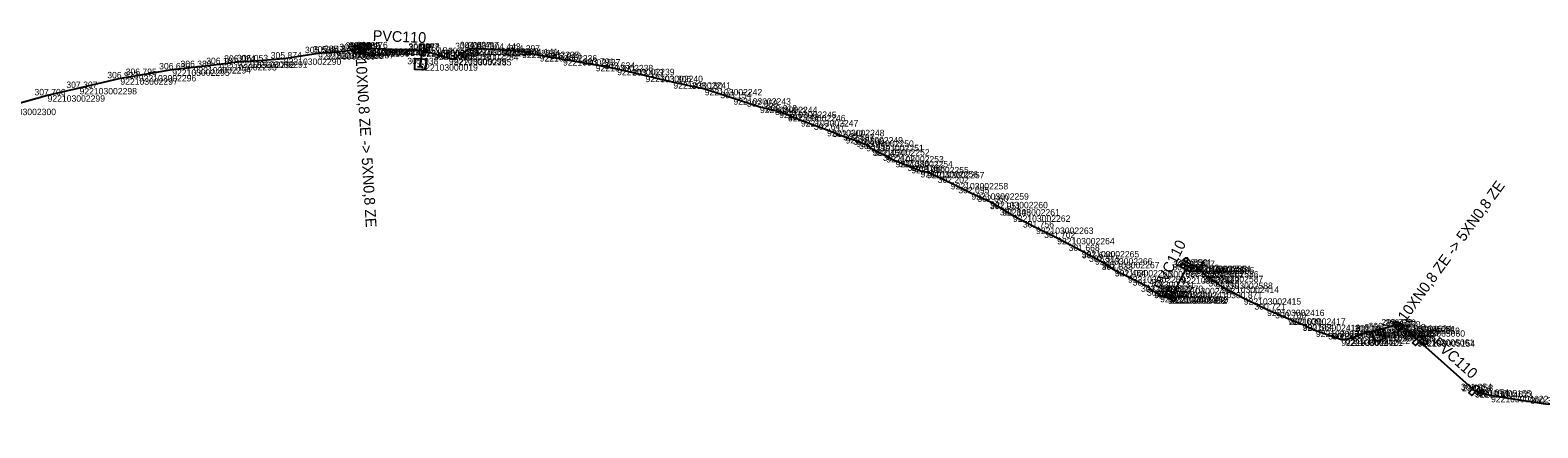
# Model space of a CAD drawing. Extents: x -771047 to -756200, y -1053876 to -1046520.
# Drawn here: x -764938.8 to -764657.5, y -1051292.3 to -1051218.1 of the extents above; entities that cross this region are included whole.
import ezdxf

# ---------------------------------------------------------------- set-up
doc = ezdxf.new("R2010")
doc.units = 0
for name, color, linetype in [('Vrstva 32', 7, 'Continuous'), ('Vrstva 33', 7, 'Continuous'), ('Vrstva 60', 7, 'Continuous'), ('Vrstva 61', 7, 'Continuous')]:
    doc.layers.add(name, color=color, linetype=linetype)

msp = doc.modelspace()

# ---------------------------------------------------------------- linework, layer by layer
at = {"layer": 'Vrstva 32'}
for p, q in [((-764876.77, -1051221.14), (-764878.3, -1051220.86)), ((-764878.3, -1051220.86), (-764878.21, -1051222.36)), ((-764878.22, -1051220.87), (-764878.29, -1051220.95)), ((-764877.76, -1051220.96), (-764878.26, -1051221.52)), ((-764877.3, -1051221.04), (-764878.23, -1051222.09)), ((-764878.21, -1051222.36), (-764876.73, -1051221.89)), ((-764876.84, -1051221.13), (-764877.82, -1051222.24)), ((-764876.74, -1051221.63), (-764877.08, -1051222)), ((-764876.73, -1051221.89), (-764876.77, -1051221.14)), ((-764684.01, -1051272.46), (-764684.46, -1051273.07)), ((-764684.46, -1051273.07), (-764683.46, -1051274.26)), ((-764684.42, -1051273.12), (-764682.95, -1051272.89)), ((-764684.17, -1051272.68), (-764683.67, -1051272.6)), ((-764684.11, -1051273.48), (-764682.74, -1051273.27)), ((-764682.57, -1051273.05), (-764684.01, -1051272.46)), ((-764683.46, -1051274.26), (-764682.57, -1051273.05)), ((-764683.82, -1051273.84), (-764683.07, -1051273.73)), ((-764683.52, -1051274.2), (-764683.41, -1051274.19))]:
    msp.add_line(p, q, dxfattribs=at)
for points in [[(-764944.66, -1051232.73), (-764935.52, -1051230.23), (-764929.56, -1051228.86), (-764921.94, -1051227.06), (-764918.5, -1051226.44), (-764912.26, -1051225.4), (-764908.27, -1051224.96), (-764903.48, -1051224.4), (-764900.12, -1051223.96), (-764897.73, -1051223.88), (-764891.44, -1051223.36), (-764885.05, -1051222.36), (-764883.55, -1051222.23), (-764881.59, -1051222.14), (-764878.72, -1051221.82), (-764877.59, -1051221.57), (-764876.8, -1051221.7), (-764875.41, -1051221.45), (-764865.7, -1051221.86), (-764863.39, -1051222.45), (-764860.65, -1051223.31), (-764859.69, -1051223.46), (-764858.36, -1051222.52), (-764857.02, -1051221.63), (-764856.16, -1051221.45), (-764854.63, -1051221.49)], [(-764865.7, -1051221.86), (-764865.96, -1051224.44)], [(-764854.63, -1051221.49), (-764850.6, -1051221.75), (-764846.99, -1051222.08), (-764843.69, -1051222.72), (-764839.35, -1051223.48), (-764833.24, -1051224.55), (-764829.25, -1051225.28), (-764823.96, -1051226.56), (-764818.76, -1051227.8), (-764812.9, -1051229.04), (-764807.55, -1051230.78), (-764802.61, -1051232.35), (-764799.02, -1051233.25), (-764797.36, -1051233.88), (-764794.97, -1051234.85), (-764790.09, -1051236.67), (-764786.64, -1051238.02), (-764784.62, -1051238.65), (-764782.76, -1051239.47), (-764781.65, -1051240.27), (-764779.02, -1051241.56), (-764777.32, -1051242.46), (-764774.36, -1051243.59), (-764772.63, -1051244.35), (-764771.43, -1051244.51), (-764767, -1051246.59), (-764763.15, -1051248.51), (-764759.6, -1051250.11), (-764757.37, -1051251.47), (-764755.4, -1051252.64), (-764751.09, -1051254.9), (-764747.14, -1051256.85), (-764742.56, -1051259.28), (-764740.09, -1051260.63), (-764738.77, -1051261.31), (-764736.4, -1051262.83), (-764733.94, -1051264.01), (-764730.63, -1051265.73), (-764729.06, -1051266.9), (-764727.95, -1051267.64), (-764726.49, -1051267.94)], [(-764726.49, -1051267.94), (-764725.88, -1051267.7), (-764725.36, -1051266.89), (-764724.89, -1051266.16), (-764723.92, -1051264.19), (-764723.2, -1051262.89), (-764722.42, -1051262.01)], [(-764722.42, -1051262.01), (-764721.74, -1051262.02), (-764721.07, -1051262.3)], [(-764721.07, -1051262.3), (-764720.29, -1051263.03), (-764719.41, -1051263.91), (-764717.63, -1051265.17), (-764716.48, -1051265.9), (-764712.34, -1051268.1), (-764707.99, -1051270.22), (-764704.04, -1051271.86), (-764701.33, -1051273.02), (-764698.88, -1051274.13), (-764694.13, -1051275.79), (-764693.4, -1051275.78), (-764692.03, -1051275.42), (-764689.4, -1051274.39), (-764689.06, -1051274.34)], [(-764666.21, -1051286.31), (-764669.16, -1051285.44), (-764680.03, -1051275.76), (-764681.76, -1051274.08), (-764682.72, -1051273.57), (-764683.56, -1051273.26), (-764684.22, -1051273.18), (-764686.59, -1051273.89), (-764687.37, -1051274.11), (-764687.19, -1051274.96)], [(-764666.21, -1051286.31), (-764669.16, -1051285.44), (-764680.03, -1051275.76), (-764681.76, -1051274.08), (-764682.72, -1051273.57), (-764683.56, -1051273.26), (-764684.22, -1051273.18)], [(-764687.37, -1051274.11), (-764689.06, -1051274.34)], [(-764687.37, -1051274.11), (-764689.06, -1051274.34)], [(-764620.08, -1051292.28), (-764622.16, -1051292.05), (-764627.63, -1051291.27), (-764632.1, -1051290.81), (-764634.75, -1051290.81), (-764636.45, -1051290.69), (-764641.04, -1051290.61), (-764649.23, -1051289.02), (-764652.42, -1051288.38), (-764656.42, -1051287.78), (-764666.21, -1051286.31)]]:
    msp.add_lwpolyline(points, dxfattribs=at)
at = {"layer": 'Vrstva 33'}
for p, q in [((-764865.49, -1051224.97), (-764866.49, -1051224.91)), ((-764865.99, -1051224.94), (-764865.93, -1051223.94)), ((-764686.72, -1051274.79), (-764687.67, -1051275.12)), ((-764686.89, -1051274.32), (-764686.56, -1051275.26))]:
    msp.add_line(p, q, dxfattribs=at)
for points in [[(-764877.18, -1051220.49), (-764876.44, -1051220.52), (-764876.52, -1051222.54), (-764877.27, -1051222.5)], [(-764866.07, -1051220.68), (-764865.33, -1051220.71), (-764865.41, -1051222.73), (-764866.16, -1051222.7)], [(-764724.12, -1051262.26), (-764723.79, -1051261.6), (-764721.99, -1051262.48), (-764722.32, -1051263.15)], [(-764727.16, -1051267.77), (-764726.84, -1051267.1), (-764725.03, -1051267.99), (-764725.36, -1051268.65)], [(-764679.43, -1051274.96), (-764678.9, -1051275.47), (-764680.3, -1051276.92), (-764680.84, -1051276.4)], [(-764668.99, -1051284.27), (-764668.43, -1051284.76), (-764669.77, -1051286.26), (-764670.32, -1051285.77)]]:
    msp.add_lwpolyline(points, close=True, dxfattribs=at)
for points in [[(-764875.97, -1051221.79), (-764875.92, -1051220.54)], [(-764875.42, -1051221.18), (-764875.94, -1051221.16)], [(-764875.92, -1051220.54), (-764875.39, -1051220.56)], [(-764875.39, -1051220.56), (-764875.24, -1051220.62), (-764875.14, -1051220.83), (-764875.14, -1051220.94), (-764875.26, -1051221.14), (-764875.42, -1051221.18)], [(-764875.41, -1051221.45), (-764865.7, -1051221.86)], [(-764864.86, -1051221.98), (-764864.81, -1051220.73)], [(-764864.31, -1051221.37), (-764864.83, -1051221.35)], [(-764864.81, -1051220.73), (-764864.29, -1051220.75)], [(-764864.29, -1051220.75), (-764864.13, -1051220.81), (-764864.03, -1051221.02), (-764864.03, -1051221.13), (-764864.15, -1051221.33), (-764864.31, -1051221.37)], [(-764865.01, -1051225.49), (-764867.01, -1051225.39), (-764866.91, -1051223.39), (-764864.91, -1051223.5), (-764865.01, -1051225.49)], [(-764726.49, -1051267.94), (-764725.88, -1051267.7), (-764725.36, -1051266.89), (-764724.89, -1051266.16), (-764723.92, -1051264.19), (-764723.2, -1051262.89), (-764722.42, -1051262.01), (-764721.74, -1051262.02)], [(-764723.57, -1051261.13), (-764723.34, -1051260.66)], [(-764722.44, -1051261.68), (-764723.57, -1051261.13)], [(-764723.34, -1051260.66), (-764723.22, -1051260.54), (-764722.99, -1051260.53), (-764722.89, -1051260.58), (-764722.75, -1051260.77), (-764722.78, -1051260.93)], [(-764722.78, -1051260.93), (-764723.01, -1051261.4)], [(-764726.61, -1051266.63), (-764726.38, -1051266.16)], [(-764725.48, -1051267.18), (-764726.61, -1051266.63)], [(-764726.38, -1051266.16), (-764726.26, -1051266.04), (-764726.03, -1051266.03), (-764725.93, -1051266.08), (-764725.79, -1051266.27), (-764725.82, -1051266.43)], [(-764725.82, -1051266.43), (-764726.05, -1051266.9)], [(-764686.59, -1051273.68), (-764685.92, -1051275.56), (-764687.8, -1051276.23), (-764688.47, -1051274.35), (-764686.59, -1051273.68)], [(-764669.16, -1051285.44), (-764680.03, -1051275.76), (-764681.76, -1051274.08), (-764682.72, -1051273.57)], [(-764679.4, -1051276.73), (-764678.52, -1051275.84)], [(-764678.58, -1051276.64), (-764678.95, -1051276.28)], [(-764678.15, -1051276.2), (-764678.07, -1051276.35), (-764678.13, -1051276.57), (-764678.21, -1051276.65), (-764678.43, -1051276.72), (-764678.58, -1051276.64)], [(-764678.52, -1051275.84), (-764678.15, -1051276.2)], [(-764668.87, -1051286.04), (-764668.04, -1051285.1)], [(-764668.06, -1051285.91), (-764668.45, -1051285.57)], [(-764667.65, -1051285.45), (-764667.56, -1051285.59), (-764667.62, -1051285.82), (-764667.69, -1051285.9), (-764667.91, -1051285.98), (-764668.06, -1051285.91)], [(-764668.04, -1051285.1), (-764667.65, -1051285.45)]]:
    msp.add_lwpolyline(points, dxfattribs=at)
at = {"layer": 'Vrstva 60'}
for p, q in [((-764885.05, -1051222.36), (-764885.05, -1051222.36)), ((-764883.55, -1051222.23), (-764883.55, -1051222.23)), ((-764881.59, -1051222.14), (-764881.59, -1051222.14)), ((-764878.72, -1051221.82), (-764878.72, -1051221.82)), ((-764877.59, -1051221.57), (-764877.59, -1051221.57)), ((-764876.85, -1051221.51), (-764876.85, -1051221.51)), ((-764876.8, -1051221.7), (-764876.8, -1051221.7)), ((-764875.41, -1051221.45), (-764875.41, -1051221.45)), ((-764865.74, -1051221.71), (-764865.74, -1051221.71)), ((-764865.7, -1051221.86), (-764865.7, -1051221.86)), ((-764863.39, -1051222.45), (-764863.39, -1051222.45)), ((-764858.36, -1051222.52), (-764858.36, -1051222.52)), ((-764857.02, -1051221.63), (-764857.02, -1051221.63)), ((-764856.16, -1051221.45), (-764856.16, -1051221.45)), ((-764854.63, -1051221.49), (-764854.63, -1051221.49)), ((-764850.6, -1051221.75), (-764850.6, -1051221.75)), ((-764846.99, -1051222.08), (-764846.99, -1051222.08)), ((-764843.69, -1051222.72), (-764843.69, -1051222.72)), ((-764912.26, -1051225.4), (-764912.26, -1051225.4)), ((-764908.27, -1051224.96), (-764908.27, -1051224.96)), ((-764903.48, -1051224.4), (-764903.48, -1051224.4)), ((-764900.12, -1051223.96), (-764900.12, -1051223.96)), ((-764897.73, -1051223.88), (-764897.73, -1051223.88)), ((-764891.44, -1051223.36), (-764891.44, -1051223.36)), ((-764865.96, -1051224.44), (-764865.96, -1051224.44)), ((-764860.65, -1051223.31), (-764860.65, -1051223.31)), ((-764859.69, -1051223.46), (-764859.69, -1051223.46)), ((-764839.35, -1051223.48), (-764839.35, -1051223.48)), ((-764833.24, -1051224.55), (-764833.24, -1051224.55)), ((-764829.25, -1051225.28), (-764829.25, -1051225.28)), ((-764921.94, -1051227.06), (-764921.94, -1051227.06)), ((-764918.5, -1051226.44), (-764918.5, -1051226.44)), ((-764823.96, -1051226.56), (-764823.96, -1051226.56)), ((-764818.76, -1051227.8), (-764818.76, -1051227.8)), ((-764935.52, -1051230.23), (-764935.52, -1051230.23)), ((-764929.56, -1051228.86), (-764929.56, -1051228.86)), ((-764812.9, -1051229.04), (-764812.9, -1051229.04)), ((-764807.55, -1051230.78), (-764807.55, -1051230.78)), ((-764802.61, -1051232.35), (-764802.61, -1051232.35)), ((-764799.02, -1051233.25), (-764799.02, -1051233.25)), ((-764797.36, -1051233.88), (-764797.36, -1051233.88)), ((-764794.97, -1051234.85), (-764794.97, -1051234.85)), ((-764790.09, -1051236.67), (-764790.09, -1051236.67)), ((-764786.64, -1051238.02), (-764786.64, -1051238.02)), ((-764784.62, -1051238.65), (-764784.62, -1051238.65)), ((-764782.76, -1051239.47), (-764782.76, -1051239.47)), ((-764781.65, -1051240.27), (-764781.65, -1051240.27)), ((-764779.02, -1051241.56), (-764779.02, -1051241.56)), ((-764777.32, -1051242.46), (-764777.32, -1051242.46)), ((-764774.36, -1051243.59), (-764774.36, -1051243.59)), ((-764772.63, -1051244.35), (-764772.63, -1051244.35)), ((-764771.43, -1051244.51), (-764771.43, -1051244.51)), ((-764767, -1051246.59), (-764767, -1051246.59)), ((-764763.15, -1051248.51), (-764763.15, -1051248.51)), ((-764759.6, -1051250.11), (-764759.6, -1051250.11)), ((-764757.37, -1051251.47), (-764757.37, -1051251.47)), ((-764755.4, -1051252.64), (-764755.4, -1051252.64)), ((-764751.09, -1051254.9), (-764751.09, -1051254.9)), ((-764747.14, -1051256.85), (-764747.14, -1051256.85)), ((-764742.56, -1051259.28), (-764742.56, -1051259.28)), ((-764740.09, -1051260.63), (-764740.09, -1051260.63)), ((-764738.77, -1051261.31), (-764738.77, -1051261.31)), ((-764722.42, -1051262.01), (-764722.42, -1051262.01)), ((-764721.74, -1051262.02), (-764721.74, -1051262.02)), ((-764736.4, -1051262.83), (-764736.4, -1051262.83)), ((-764733.94, -1051264.01), (-764733.94, -1051264.01)), ((-764723.92, -1051264.19), (-764723.92, -1051264.19)), ((-764723.2, -1051262.89), (-764723.2, -1051262.89)), ((-764723.06, -1051262.37), (-764723.06, -1051262.37)), ((-764721.07, -1051262.3), (-764721.07, -1051262.3)), ((-764720.29, -1051263.03), (-764720.29, -1051263.03)), ((-764719.41, -1051263.91), (-764719.41, -1051263.91)), ((-764730.63, -1051265.73), (-764730.63, -1051265.73)), ((-764729.06, -1051266.9), (-764729.06, -1051266.9)), ((-764727.95, -1051267.64), (-764727.95, -1051267.64)), ((-764726.1, -1051267.88), (-764726.1, -1051267.88)), ((-764725.88, -1051267.7), (-764725.88, -1051267.7)), ((-764725.36, -1051266.89), (-764725.36, -1051266.89)), ((-764724.89, -1051266.16), (-764724.89, -1051266.16)), ((-764717.63, -1051265.17), (-764717.63, -1051265.17)), ((-764716.48, -1051265.9), (-764716.48, -1051265.9)), ((-764726.49, -1051267.94), (-764726.49, -1051267.94)), ((-764712.34, -1051268.1), (-764712.34, -1051268.1)), ((-764707.99, -1051270.22), (-764707.99, -1051270.22)), ((-764704.04, -1051271.86), (-764704.04, -1051271.86)), ((-764701.33, -1051273.02), (-764701.33, -1051273.02)), ((-764684.22, -1051273.18), (-764684.22, -1051273.18)), ((-764683.56, -1051273.26), (-764683.56, -1051273.26)), ((-764698.88, -1051274.13), (-764698.88, -1051274.13)), ((-764694.13, -1051275.79), (-764694.13, -1051275.79)), ((-764693.4, -1051275.78), (-764693.4, -1051275.78)), ((-764692.03, -1051275.42), (-764692.03, -1051275.42)), ((-764689.4, -1051274.39), (-764689.4, -1051274.39)), ((-764689.06, -1051274.34), (-764689.06, -1051274.34)), ((-764687.37, -1051274.11), (-764687.37, -1051274.11)), ((-764687.19, -1051274.96), (-764687.19, -1051274.96)), ((-764686.59, -1051273.89), (-764686.59, -1051273.89)), ((-764682.72, -1051273.57), (-764682.72, -1051273.57)), ((-764681.76, -1051274.08), (-764681.76, -1051274.08)), ((-764680.03, -1051275.76), (-764680.03, -1051275.76)), ((-764679.87, -1051275.94), (-764679.87, -1051275.94)), ((-764669.38, -1051285.26), (-764669.38, -1051285.26)), ((-764669.16, -1051285.44), (-764669.16, -1051285.44)), ((-764666.21, -1051286.31), (-764666.21, -1051286.31))]:
    msp.add_line(p, q, dxfattribs=at)

# ---------------------------------------------------------------- texts
at = {"layer": 'Vrstva 32'}
for rotation, p in [(273.461, (-764878.04, -1051223.41)), (53.8543, (-764682.15, -1051272.6))]:
    msp.add_text('10XN0,8 ZE -> 5XN0,8 ZE', height=2, rotation=rotation, dxfattribs=at).set_placement(p)
at = {"layer": 'Vrstva 33'}
for rotation, p in [(357.5706, (-764874.88, -1051220.06)), (63.8315, (-764727.43, -1051266.81)), (318.3416, (-764677.27, -1051276.64))]:
    msp.add_text('PVC110', height=2, rotation=rotation, dxfattribs=at).set_placement(p)
at = {"layer": 'Vrstva 60'}
for s, p in [('922103002289', (-764885.05, -1051223.56)), ('922103002288', (-764883.55, -1051223.43)), ('922103002287', (-764881.59, -1051223.34)), ('922103002286', (-764878.72, -1051223.02)), ('922103005062', (-764877.59, -1051222.77)), ('922103005151', (-764876.85, -1051222.71)), ('922103004987', (-764876.8, -1051222.9)), ('922103005058', (-764875.41, -1051222.65)), ('922103005150', (-764865.74, -1051222.91)), ('922103005057', (-764865.7, -1051223.06)), ('922103005056', (-764863.39, -1051223.65)), ('922103002284', (-764858.36, -1051223.72)), ('922103002283', (-764857.02, -1051222.83)), ('922103002282', (-764856.16, -1051222.65)), ('922103002233', (-764854.63, -1051222.69)), ('922103002234', (-764850.6, -1051222.95)), ('922103002235', (-764846.99, -1051223.28)), ('922103002236', (-764843.69, -1051223.92)), ('922103002295', (-764912.26, -1051226.6)), ('922103002294', (-764908.27, -1051226.16)), ('922103002293', (-764903.48, -1051225.59)), ('922103002292', (-764900.12, -1051225.16)), ('922103002291', (-764897.73, -1051225.08)), ('922103002290', (-764891.44, -1051224.56)), ('922103000019', (-764865.96, -1051225.64)), ('922103005055', (-764860.65, -1051224.51)), ('922103002285', (-764859.69, -1051224.66)), ('922103002237', (-764839.35, -1051224.68)), ('922103002238', (-764833.24, -1051225.75)), ('922103002239', (-764829.25, -1051226.48)), ('922103002297', (-764921.94, -1051228.26)), ('922103002296', (-764918.5, -1051227.64)), ('922103002240', (-764823.96, -1051227.77)), ('922103002241', (-764818.76, -1051229)), ('922103002299', (-764935.52, -1051231.43)), ('922103002298', (-764929.56, -1051230.06)), ('922103002242', (-764812.9, -1051230.24)), ('922103002243', (-764807.55, -1051231.98)), ('922103002300', (-764944.66, -1051233.93)), ('922103002244', (-764802.61, -1051233.55)), ('922103002245', (-764799.02, -1051234.45)), ('922103002246', (-764797.36, -1051235.08)), ('922103002247', (-764794.97, -1051236.05)), ('922103002248', (-764790.09, -1051237.87)), ('922103002249', (-764786.64, -1051239.22)), ('922103002250', (-764784.62, -1051239.85)), ('922103002251', (-764782.76, -1051240.67)), ('922103002252', (-764781.65, -1051241.47)), ('922103002253', (-764779.02, -1051242.76)), ('922103002254', (-764777.32, -1051243.66)), ('922103002255', (-764774.36, -1051244.79)), ('922103002256', (-764772.63, -1051245.55)), ('922103002257', (-764771.43, -1051245.71)), ('922103002258', (-764767, -1051247.79)), ('922103002259', (-764763.15, -1051249.71)), ('922103002260', (-764759.6, -1051251.31)), ('922103002261', (-764757.37, -1051252.67)), ('922103002262', (-764755.4, -1051253.84)), ('922103002263', (-764751.09, -1051256.1)), ('922103002264', (-764747.14, -1051258.05)), ('922103002265', (-764742.56, -1051260.48)), ('922103002266', (-764740.09, -1051261.83)), ('922103002267', (-764738.77, -1051262.51)), ('922103002583', (-764722.42, -1051263.21)), ('922103002584', (-764721.74, -1051263.22)), ('922103002268', (-764736.4, -1051264.03)), ('922103002269', (-764733.94, -1051265.21)), ('922103002412', (-764723.92, -1051265.39)), ('922103002413', (-764723.2, -1051264.09)), ('922103005153', (-764723.06, -1051263.57)), ('922103002585', (-764721.07, -1051263.5)), ('922103002586', (-764720.29, -1051264.23)), ('922103002587', (-764719.41, -1051265.11)), ('922103002270', (-764730.63, -1051266.93)), ('922103002271', (-764729.06, -1051268.1)), ('922103002272', (-764727.95, -1051268.84)), ('922103005152', (-764726.1, -1051269.08)), ('922103002409', (-764725.88, -1051268.9)), ('922103002410', (-764725.36, -1051268.08)), ('922103002411', (-764724.89, -1051267.36)), ('922103002588', (-764717.63, -1051266.37)), ('922103002414', (-764716.48, -1051267.1)), ('922103002408', (-764726.49, -1051269.14)), ('922103002415', (-764712.34, -1051269.3)), ('922103002416', (-764707.99, -1051271.42)), ('922103002417', (-764704.04, -1051273.06)), ('922103002418', (-764701.33, -1051274.22)), ('922103004624', (-764684.22, -1051274.38)), ('922103005051', (-764683.56, -1051274.46)), ('922103002419', (-764698.88, -1051275.33)), ('922103002420', (-764694.13, -1051276.99)), ('922103002421', (-764693.4, -1051276.98)), ('922103002422', (-764692.03, -1051276.62)), ('922103002423', (-764689.4, -1051275.59)), ('922103004626', (-764689.06, -1051275.54)), ('922103004625', (-764687.37, -1051275.31)), ('922103000005', (-764687.19, -1051276.16)), ('922103002589', (-764686.59, -1051275.09)), ('922103005059', (-764682.72, -1051274.77)), ('922103005060', (-764681.76, -1051275.28)), ('922103005061', (-764680.03, -1051276.96)), ('922103005154', (-764679.87, -1051277.14)), ('922103005155', (-764669.38, -1051286.46)), ('922103004623', (-764669.16, -1051286.64)), ('922103004622', (-764666.21, -1051287.51))]:
    msp.add_text(s, height=1.2, dxfattribs=at).set_placement(p)
at = {"layer": 'Vrstva 61'}
for s, p in [('306.024', (-764902.57, -1051223.96)), ('306.053', (-764900.18, -1051223.88)), ('305.874', (-764893.89, -1051223.36)), ('305.538', (-764887.5, -1051222.36)), ('305.447', (-764886, -1051222.23)), ('305.371', (-764883.95, -1051222.14)), ('305.331', (-764881.08, -1051221.82)), ('304.941', (-764879.94, -1051221.57)), ('306.238', (-764879.31, -1051221.51)), ('305.240', (-764879.25, -1051221.7)), ('304.476', (-764877.86, -1051221.45)), ('306.077', (-764868.2, -1051221.71)), ('304.578', (-764868.15, -1051221.86)), ('305.184', (-764865.84, -1051222.45)), ('305.150', (-764863.1, -1051223.31)), ('305.098', (-764862.14, -1051223.46)), ('304.864', (-764860.81, -1051222.52)), ('304.708', (-764859.48, -1051221.63)), ('304.627', (-764858.61, -1051221.45)), ('304.487', (-764857.09, -1051221.49)), ('304.443', (-764853.05, -1051221.75)), ('304.297', (-764849.44, -1051222.08)), ('304.141', (-764846.05, -1051222.72)), ('303.940', (-764841.8, -1051223.48)), ('306.795', (-764920.95, -1051226.44)), ('306.630', (-764914.71, -1051225.4)), ('306.380', (-764910.72, -1051224.96)), ('306.187', (-764905.93, -1051224.4)), ('305.938', (-764868.41, -1051224.44)), ('303.791', (-764835.6, -1051224.55)), ('303.634', (-764831.7, -1051225.28)), ('303.463', (-764826.41, -1051226.56)), ('307.307', (-764932.02, -1051228.86)), ('306.923', (-764924.39, -1051227.06)), ('303.306', (-764821.22, -1051227.8)), ('303.180', (-764815.35, -1051229.04)), ('307.706', (-764937.97, -1051230.23)), ('303.154', (-764810, -1051230.78)), ('302.958', (-764805.06, -1051232.35)), ('302.918', (-764801.48, -1051233.25)), ('302.913', (-764799.81, -1051233.88)), ('302.742', (-764797.42, -1051234.85)), ('302.647', (-764792.54, -1051236.67)), ('302.542', (-764789.08, -1051238.02)), ('302.597', (-764787.07, -1051238.65)), ('302.500', (-764785.21, -1051239.47)), ('302.458', (-764784.11, -1051240.27)), ('302.454', (-764781.47, -1051241.56)), ('302.421', (-764779.67, -1051242.46)), ('302.386', (-764776.81, -1051243.59)), ('302.416', (-764775.08, -1051244.35)), ('302.266', (-764773.88, -1051244.51)), ('302.202', (-764769.45, -1051246.59)), ('302.095', (-764765.6, -1051248.51)), ('302.060', (-764762.05, -1051250.11)), ('301.951', (-764759.72, -1051251.47)), ('301.848', (-764757.85, -1051252.64)), ('301.756', (-764753.55, -1051254.9)), ('301.702', (-764749.58, -1051256.85)), ('301.668', (-764745.02, -1051259.28)), ('301.644', (-764742.54, -1051260.63)), ('301.515', (-764741.22, -1051261.31)), ('301.533', (-764738.85, -1051262.83)), ('301.019', (-764725.65, -1051262.89)), ('301.914', (-764725.51, -1051262.37)), ('300.850', (-764724.87, -1051262.01)), ('300.811', (-764724.1, -1051262.02)), ('300.777', (-764723.52, -1051262.3)), ('300.793', (-764722.74, -1051263.03)), ('301.464', (-764736.39, -1051264.01)), ('301.400', (-764733.08, -1051265.73)), ('300.731', (-764727.24, -1051266.16)), ('300.680', (-764726.37, -1051264.19)), ('300.881', (-764721.77, -1051263.91)), ('300.952', (-764720.08, -1051265.17)), ('300.963', (-764718.93, -1051265.9)), ('301.380', (-764731.51, -1051266.9)), ('301.417', (-764730.4, -1051267.64)), ('301.096', (-764728.95, -1051267.94)), ('302.369', (-764728.55, -1051267.88)), ('301.105', (-764728.34, -1051267.7)), ('300.810', (-764727.81, -1051266.89)), ('300.871', (-764714.7, -1051268.1)), ('300.721', (-764710.35, -1051270.22)), ('300.700', (-764706.49, -1051271.86)), ('300.609', (-764703.78, -1051273.02)), ('300.564', (-764701.33, -1051274.13)), ('300.101', (-764691.76, -1051274.39)), ('300.249', (-764691.51, -1051274.34)), ('300.040', (-764689.82, -1051274.11)), ('300.372', (-764689.04, -1051273.89)), ('299.723', (-764686.67, -1051273.18)), ('299.530', (-764686.01, -1051273.26)), ('299.578', (-764685.18, -1051273.57)), ('299.760', (-764684.21, -1051274.08)), ('300.349', (-764696.58, -1051275.79)), ('300.323', (-764695.85, -1051275.78)), ('300.195', (-764694.49, -1051275.42)), ('300.508', (-764689.65, -1051274.96)), ('299.890', (-764682.48, -1051275.76)), ('299.954', (-764682.32, -1051275.94)), ('301.054', (-764671.83, -1051285.26)), ('299.858', (-764671.61, -1051285.44)), ('300.074', (-764668.66, -1051286.31)), ('300.393', (-764658.87, -1051287.78))]:
    msp.add_text(s, height=1.2, dxfattribs=at).set_placement(p)

doc.saveas('drawing.dxf')
